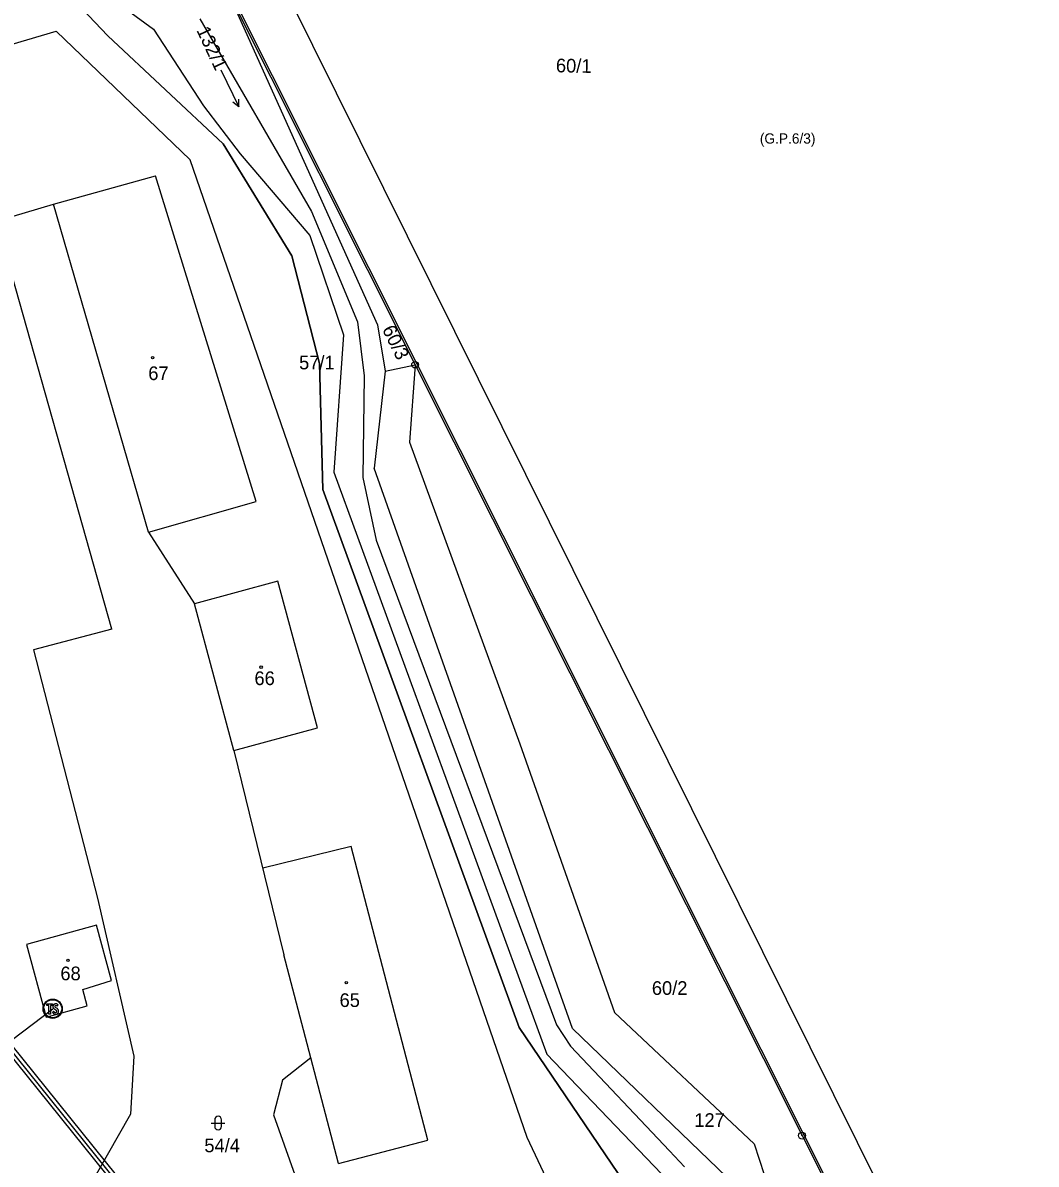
# Model space of a CAD drawing. Extents: x -555757 to -553364, y -1100723 to -1096439.
# Drawn here: x -554203.1 to -554054.8, y -1097200.1 to -1097033.1 of the extents above; entities that cross this region are included whole.
import ezdxf

# ---------------------------------------------------------------- set-up
doc = ezdxf.new("R2010")
doc.units = 0
for name, color, linetype in [('00_NÁVRH - 0.18 mm', 7, 'Continuous'), ('01_HLADINA', 7, 'Continuous'), ('02_ČÁRA - 0.35 mm', 7, 'Continuous'), ('05_SÍTĚ - vedení VN - nadzemní', 7, 'Continuous'), ('BUDOVY', 7, 'Continuous'), ('C$SLO$PARCELY', 7, 'Continuous'), ('HRANICE$PARCELY', 7, 'Continuous'), ('POPIS', 7, 'Continuous'), ('SLOUPY', 7, 'Continuous'), ('Stanice', 7, 'Continuous'), ('ZNA$KY$KULTUR', 7, 'Continuous'), ('zájem', 7, 'Continuous')]:
    doc.layers.add(name, color=color, linetype=linetype)

# ---------------------------------------------------------------- blocks, each defined once
blk = doc.blocks.new('4$02')
at = {"layer": 'SLOUPY'}
blk.add_circle((0, 0), 0.175, dxfattribs=at)
blk = doc.blocks.new('1$05')
at = {"layer": 'SLOUPY'}
for radius in [0.5, 0.032]:
    blk.add_circle((0, 0), radius, dxfattribs=at)
blk = doc.blocks.new('3$16')
at = {"layer": 'ZNA$KY$KULTUR'}
for p, q in [((-1, 1), (1, 1)), ((-0.5, 1.5), (-0.5, 0.5)), ((0.5, 0.5), (0.5, 1.5))]:
    blk.add_line(p, q, dxfattribs=at)
for centre, start, end in [((0, 1.5), 0, 180), ((0, 0.5), 180, 359.9879)]:
    blk.add_arc(centre, 0.5, start, end, dxfattribs=at)
blk = doc.blocks.new('8$02')
at = {"layer": 'ZNA$KY$KULTUR'}
for p, q in [((0.864, 2.855), (-0.89, -2.882)), ((-0.89, -2.882), (-1.083, -1.802)), ((-0.89, -2.882), (-0.125, -2.095))]:
    blk.add_line(p, q, dxfattribs=at)
blk = doc.blocks.new('DGN_COMPLEXSHAPE1')
at = {"layer": 'Stanice'}
for p, q in [((-554198.6, -1097176.8), (-554198.6, -1097176.8)), ((-554198.49, -1097176.69), (-554198.49, -1097176.69)), ((-554198.24, -1097176.61), (-554198.24, -1097176.61)), ((-554198.1, -1097176.64), (-554198.1, -1097176.64)), ((-554197.99, -1097176.7), (-554197.99, -1097176.7)), ((-554198.66, -1097176.99), (-554198.66, -1097176.99)), ((-554198.65, -1097177.17), (-554198.65, -1097177.17)), ((-554198.55, -1097177.32), (-554198.55, -1097177.32)), ((-554198.42, -1097177.41), (-554198.42, -1097177.41)), ((-554198.37, -1097178.14), (-554198.37, -1097178.14)), ((-554198.36, -1097177.89), (-554198.36, -1097177.89)), ((-554198.21, -1097177.51), (-554198.21, -1097177.51)), ((-554198.13, -1097177.6), (-554198.13, -1097177.6)), ((-554198.11, -1097176.89), (-554198.11, -1097176.89)), ((-554198.09, -1097177.27), (-554198.09, -1097177.27)), ((-554198.05, -1097178.09), (-554198.05, -1097178.09)), ((-554197.86, -1097177.57), (-554197.86, -1097177.57))]:
    blk.add_line(p, q, dxfattribs=at)
for points in [[(-554198.11, -1097176.89), (-554198.03, -1097176.97), (-554197.89, -1097176.78), (-554197.95, -1097176.73), (-554197.99, -1097176.7)], [(-554198.46, -1097177.84), (-554198.5, -1097177.79), (-554198.54, -1097177.73), (-554198.56, -1097177.71), (-554198.73, -1097177.88), (-554198.65, -1097177.98), (-554198.6, -1097178.03), (-554198.52, -1097178.08)], [(-554198.42, -1097177.41), (-554198.33, -1097177.46), (-554198.27, -1097177.48), (-554198.21, -1097177.51)], [(-554198.09, -1097177.27), (-554198.16, -1097177.23), (-554198.24, -1097177.2), (-554198.28, -1097177.17), (-554198.32, -1097177.15)]]:
    blk.add_lwpolyline(points, dxfattribs=at)
for centre, radius, start, end in [((-554198.24, -1097177.03), 0.426, 147.606, 174.6263), ((-554198.28, -1097176.99), 0.366, 125.3321, 148.6112), ((-554198.26, -1097176.99), 0.376, 87.335, 128.8937), ((-554198.22, -1097177.03), 0.178, 51.0231, 133.2588), ((-554198.24, -1097176.96), 0.346, 67.1502, 90.8442), ((-554198.21, -1097176.99), 0.372, 52.7961, 72.3697), ((-554198.28, -1097177.05), 0.384, 171.2946, 186.7212), ((-554198.39, -1097177.08), 0.273, 182.1561, 198.0304), ((-554198.38, -1097177.11), 0.274, 192.3253, 230.929), ((-554198.17, -1097176.92), 0.552, 226.4757, 243.728), ((-554198.33, -1097177.81), 0.331, 234.7382, 263.9399), ((-554198.32, -1097177.7), 0.198, 223.9056, 258.8012), ((-554198.22, -1097177.02), 0.176, 136.4395, 193.2806), ((-554198.2, -1097176.99), 0.199, 201.1532, 233.8944), ((-554198.29, -1097177.62), 0.523, 261.7682, 297.0049), ((-554198.3, -1097177.73), 0.177, 250.7464, 318.0281), ((-554198.37, -1097177.75), 0.284, 32.0683, 55.934), ((-554198.34, -1097177.69), 0.228, 318.5901, 24.9033), ((-554198.35, -1097177.77), 0.564, 42.6409, 62.3474), ((-554198.27, -1097177.73), 0.416, 301.7784, 355.1456), ((-554198.18, -1097177.59), 0.326, 4.6329, 39.3142), ((-554198.27, -1097177.67), 0.425, 346.8227, 14.6036)]:
    blk.add_arc(centre, radius, start, end, dxfattribs=at)
blk = doc.blocks.new('CEZ00351')
at = {"layer": 'Stanice'}
for p, q in [((-0.85, 0.7), (-0.04, 0.7)), ((-0.85, 0.46), (-0.85, 0.7)), ((-0.57, 0.46), (-0.85, 0.46)), ((-0.57, -0.78), (-0.57, 0.46)), ((-0.04, 0.46), (-0.31, 0.46)), ((-0.31, 0.46), (-0.31, -0.78)), ((-0.04, 0.7), (-0.04, 0.46)), ((0.04, 0.35), (0.04, 0.35)), ((0.06, 0.17), (0.06, 0.17)), ((0.11, 0.54), (0.11, 0.54)), ((0.15, 0.02), (0.15, 0.02)), ((0.21, 0.64), (0.21, 0.64)), ((0.42, 0.16), (0.38, 0.19)), ((0.47, 0.14), (0.42, 0.16)), ((0.46, 0.73), (0.46, 0.73)), ((0.55, 0.11), (0.47, 0.14)), ((0.62, 0.07), (0.55, 0.11)), ((0.59, 0.45), (0.59, 0.45)), ((0.59, 0.45), (0.68, 0.36)), ((0.6, 0.7), (0.6, 0.7)), ((0.62, 0.07), (0.62, 0.07)), ((0.68, 0.36), (0.81, 0.56)), ((0.76, 0.61), (0.71, 0.64)), ((0.71, 0.64), (0.71, 0.64)), ((0.81, 0.56), (0.76, 0.61)), ((-0.31, -0.78), (-0.57, -0.78)), ((0.14, -0.37), (-0.03, -0.55)), ((-0.03, -0.55), (0.05, -0.64)), ((0.05, -0.64), (0.11, -0.7)), ((0.11, -0.7), (0.18, -0.75)), ((0.17, -0.4), (0.14, -0.37)), ((0.2, -0.46), (0.17, -0.4)), ((0.24, -0.5), (0.2, -0.46)), ((0.29, -0.08), (0.29, -0.08)), ((0.29, -0.08), (0.37, -0.12)), ((0.34, -0.8), (0.34, -0.8)), ((0.35, -0.56), (0.35, -0.56)), ((0.37, -0.12), (0.44, -0.15)), ((0.44, -0.15), (0.49, -0.18)), ((0.49, -0.18), (0.49, -0.18)), ((0.57, -0.26), (0.57, -0.26)), ((0.65, -0.75), (0.65, -0.75)), ((0.84, -0.23), (0.84, -0.23))]:
    blk.add_line(p, q, dxfattribs=at)
blk.add_lwpolyline([(-0.85, 0.7), (-0.04, 0.7), (-0.04, 0.46), (-0.31, 0.46), (-0.31, -0.78), (-0.57, -0.78), (-0.57, 0.46), (-0.85, 0.46), (-0.85, 0.7)], dxfattribs=at)
for radius in [1.41, 1.32]:
    blk.add_circle((0, 0), radius, dxfattribs=at)
for centre, radius, start, end in [((0.47, 0.31), 0.426, 147.606, 174.6263), ((0.42, 0.29), 0.384, 171.2946, 186.7212), ((0.32, 0.25), 0.273, 182.1561, 198.0304), ((0.32, 0.23), 0.274, 192.3253, 230.929), ((0.42, 0.34), 0.366, 125.3321, 148.6112), ((0.53, 0.42), 0.552, 226.4757, 243.728), ((0.45, 0.35), 0.376, 87.335, 128.8937), ((0.49, 0.32), 0.176, 136.4395, 193.2806), ((0.5, 0.35), 0.199, 201.1532, 233.8944), ((0.48, 0.31), 0.178, 51.0231, 133.2588), ((0.47, 0.38), 0.346, 67.1502, 90.8442), ((0.49, 0.34), 0.372, 52.7961, 72.3697), ((0.36, -0.43), 0.564, 42.6409, 62.3474), ((0.37, -0.47), 0.331, 234.7382, 263.9399), ((0.39, -0.36), 0.198, 223.9056, 258.8012), ((0.41, -0.29), 0.523, 261.7682, 297.0049), ((0.41, -0.39), 0.177, 250.7464, 318.0281), ((0.33, -0.41), 0.284, 32.0683, 55.934), ((0.37, -0.36), 0.228, 318.5901, 24.9033), ((0.43, -0.4), 0.416, 301.7784, 355.1456), ((0.52, -0.26), 0.326, 4.6329, 39.3142), ((0.43, -0.34), 0.425, 346.8227, 14.6036)]:
    blk.add_arc(centre, radius, start, end, dxfattribs=at)
blk.add_blockref('DGN_COMPLEXSHAPE1', (554198.7, 1097177.34), dxfattribs=at)

msp = doc.modelspace()

# ---------------------------------------------------------------- linework, layer by layer
at = {"layer": '00_NÁVRH - 0.18 mm'}
msp.add_lwpolyline([(-554072.39, -1097347.97), (-554212.16, -1097174.33), (-554215.46, -1097170.85), (-554215.92, -1097170.1), (-554216.03, -1097169.32), (-554216.12, -1097162.57), (-554216.12, -1097142.44), (-554216.99, -1097122.51), (-554215.34, -1097112.06), (-554214.14, -1097105.13), (-554213.97, -1097104.07), (-554216.11, -1097086.78), (-554218.43, -1097068.38), (-554223.18, -1097052.33), (-554232.35, -1097041.38), (-554240.57, -1097025.02)], dxfattribs=at)
at = {"layer": '01_HLADINA'}
for p, q in [((-554177.18, -1097032.47), (-554160.83, -1097060.69)), ((-554160.83, -1097060.69), (-554154.12, -1097076.85)), ((-554154.12, -1097076.85), (-554153.14, -1097084.72)), ((-554153.14, -1097084.72), (-554153.34, -1097099.63)), ((-554153.34, -1097099.63), (-554151.39, -1097108.76)), ((-554151.39, -1097108.76), (-554124.97, -1097179.7)), ((-554124.97, -1097179.7), (-554122.95, -1097182.83)), ((-554122.95, -1097182.83), (-554108.44, -1097198.14)), ((-554108.44, -1097198.14), (-554106.24, -1097200.47))]:
    msp.add_line(p, q, dxfattribs=at)
at = {"layer": '02_ČÁRA - 0.35 mm'}
for points in [[(-554212.51, -1097174.72), (-554072.8, -1097348.28), (-554066.66, -1097356.73), (-554065.77, -1097358.43)], [(-554211.78, -1097173.99), (-554211.77, -1097173.99), (-554071.98, -1097347.66), (-554065.79, -1097356.19), (-554064.76, -1097358.14)]]:
    msp.add_lwpolyline(points, dxfattribs=at)
at = {"layer": '05_SÍTĚ - vedení VN - nadzemní'}
msp.add_lwpolyline([(-554223.92, -1097196.49), (-554198.7, -1097177.33)], dxfattribs=at)
at = {"layer": 'HRANICE$PARCELY'}
for p, q in [((-554195.37, -1097025.58), (-554183.95, -1097034.02)), ((-554173.81, -1097026.99), (-554151.18, -1097077.29)), ((-554218.71, -1097040.33), (-554198.18, -1097034.31)), ((-554198.18, -1097034.31), (-554178.57, -1097053.11)), ((-554183.95, -1097034.02), (-554176.64, -1097045.2)), ((-554176.64, -1097045.2), (-554171.26, -1097052.26)), ((-554129.28, -1097196.2), (-554178.57, -1097053.11)), ((-554171.26, -1097052.26), (-554161.09, -1097064.19)), ((-554198.58, -1097059.6), (-554183.65, -1097055.47)), ((-554168.92, -1097103.12), (-554183.65, -1097055.47)), ((-554206.91, -1097062.09), (-554198.58, -1097059.6)), ((-554184.67, -1097107.59), (-554198.58, -1097059.6)), ((-554190.03, -1097121.81), (-554206.91, -1097062.09)), ((-554161.09, -1097064.19), (-554156.15, -1097078.75)), ((-554151.18, -1097077.29), (-554150.06, -1097084.05)), ((-554156.15, -1097078.75), (-554157.58, -1097098.82)), ((-554150.06, -1097084.05), (-554145.67, -1097083.12)), ((-554145.67, -1097083.12), (-554146.49, -1097094.46)), ((-554150.06, -1097084.05), (-554151.65, -1097098.22)), ((-554146.49, -1097094.46), (-554130.37, -1097138.56)), ((-554122.67, -1097180.21), (-554151.65, -1097098.22)), ((-554157.58, -1097098.82), (-554126.39, -1097183.96)), ((-554184.67, -1097107.59), (-554168.92, -1097103.12)), ((-554184.67, -1097107.59), (-554177.97, -1097118.07)), ((-554165.74, -1097114.77), (-554177.97, -1097118.07)), ((-554159.95, -1097136.23), (-554165.74, -1097114.77)), ((-554172.18, -1097139.53), (-554177.97, -1097118.07)), ((-554190.03, -1097121.81), (-554201.49, -1097124.84)), ((-554201.49, -1097124.84), (-554192.13, -1097161.14)), ((-554172.18, -1097139.53), (-554159.95, -1097136.23)), ((-554172.18, -1097139.53), (-554164.86, -1097169.43)), ((-554130.37, -1097138.56), (-554116.49, -1097177.88)), ((-554155.04, -1097153.61), (-554167.96, -1097156.77)), ((-554143.82, -1097196.57), (-554155.04, -1097153.61)), ((-554192.13, -1097161.14), (-554186.81, -1097184.27)), ((-554192.28, -1097165.12), (-554202.55, -1097167.92)), ((-554190.08, -1097173.19), (-554192.28, -1097165.12)), ((-554202.55, -1097167.92), (-554199.67, -1097178.58)), ((-554160.92, -1097184.51), (-554164.86, -1097169.43)), ((-554194.28, -1097174.5), (-554190.08, -1097173.19)), ((-554193.65, -1097176.92), (-554194.28, -1097174.5)), ((-554199.67, -1097178.58), (-554193.65, -1097176.92)), ((-554116.49, -1097177.88), (-554096.05, -1097197.12)), ((-554100.07, -1097201.98), (-554122.67, -1097180.21)), ((-554186.81, -1097184.27), (-554187.32, -1097192.75)), ((-554160.92, -1097184.51), (-554165.09, -1097187.79)), ((-554156.88, -1097199.98), (-554160.92, -1097184.51)), ((-554126.39, -1097183.96), (-554106.26, -1097205)), ((-554165.09, -1097187.79), (-554166.39, -1097192.85)), ((-554187.32, -1097192.75), (-554192.36, -1097201.57)), ((-554166.39, -1097192.85), (-554157.92, -1097216.62)), ((-554156.88, -1097199.98), (-554143.82, -1097196.57)), ((-554102.74, -1097251.85), (-554129.28, -1097196.2)), ((-554096.05, -1097197.12), (-554071.94, -1097270.57))]:
    msp.add_line(p, q, dxfattribs=at)
msp.add_lwpolyline([(-554173.81, -1097026.99), (-554145.67, -1097083.12), (-554089.07, -1097195.9), (-554032.42, -1097308.7)], dxfattribs=at)
at = {"layer": 'POPIS'}
msp.add_line((-554165.1, -1097027.42), (-554028.6, -1097302.46), dxfattribs=at)
msp.add_lwpolyline([(-554173.65, -1097026.65), (-554145.4, -1097082.99), (-554088.8, -1097195.77), (-554032.27, -1097308.33)], dxfattribs=at)
at = {"layer": 'zájem'}
for points in [[(-554055.91, -1097333.12), (-554068.1, -1097310.12), (-554076.3, -1097297.37), (-554083.64, -1097283.44), (-554094.93, -1097256.14), (-554100.02, -1097244.94), (-554114.01, -1097204.34), (-554130.46, -1097180.06), (-554159.17, -1097101.34), (-554159.64, -1097082.93), (-554163.72, -1097067.19), (-554173.74, -1097050.79), (-554190.63, -1097034.96), (-554197.16, -1097028.05)], [(-554197.16, -1097028.05), (-554190.63, -1097034.96), (-554173.74, -1097050.79), (-554163.72, -1097067.19), (-554159.64, -1097082.93), (-554159.17, -1097101.34), (-554130.46, -1097180.06), (-554114.01, -1097204.34), (-554100.02, -1097244.94), (-554094.93, -1097256.14), (-554083.64, -1097283.44), (-554076.3, -1097297.37), (-554068.1, -1097310.12), (-554055.91, -1097333.12)]]:
    msp.add_lwpolyline(points, dxfattribs=at)

# ---------------------------------------------------------------- block references
msp.add_blockref('CEZ00351', (-554198.7, -1097177.34))
at = {"layer": 'BUDOVY'}
msp.add_blockref('4$02', (-554155.75, -1097173.51), dxfattribs=at)
at = {"layer": 'SLOUPY'}
for name, p in [('4$02', (-554184.09, -1097082.06)), ('1$05', (-554145.67, -1097083.12)), ('4$02', (-554168.2, -1097127.36)), ('4$02', (-554196.47, -1097170.27)), ('1$05', (-554089.07, -1097195.9))]:
    msp.add_blockref(name, p, dxfattribs=at)
at = {"layer": 'ZNA$KY$KULTUR', "xscale": 0.9999980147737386, "yscale": 0.9999980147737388, "rotation": 43.291998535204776}
msp.add_blockref('8$02', (-554172.79, -1097042.65), dxfattribs=at)
at = {"layer": 'ZNA$KY$KULTUR'}
msp.add_blockref('3$16', (-554174.5, -1097195.07), dxfattribs=at)

# ---------------------------------------------------------------- texts
at = {"layer": 'C$SLO$PARCELY'}
for s, rotation, p in [('132/1', 295.0469, (-554177.7, -1097034.16)), ('60/1', 358.9029, (-554125.09, -1097040.31)), ('60/3', 296.2024, (-554150.55, -1097077.92))]:
    msp.add_text(s, height=2, rotation=rotation, dxfattribs=at).set_placement(p)
for s, p in [('67', (-554184.71, -1097085.35)), ('57/1', (-554162.65, -1097083.78)), ('66', (-554169.18, -1097129.98)), ('68', (-554197.57, -1097173.17)), ('60/2', (-554111.04, -1097175.31)), ('65', (-554156.73, -1097177.08)), ('127', (-554104.83, -1097194.63)), ('54/4', (-554176.51, -1097198.34))]:
    msp.add_text(s, height=2, dxfattribs=at).set_placement(p)
at = {"layer": 'POPIS'}
msp.add_text('(G.P.6/3)', height=1.5, dxfattribs=at).set_placement((-554095.24, -1097050.75))

doc.saveas('drawing.dxf')
